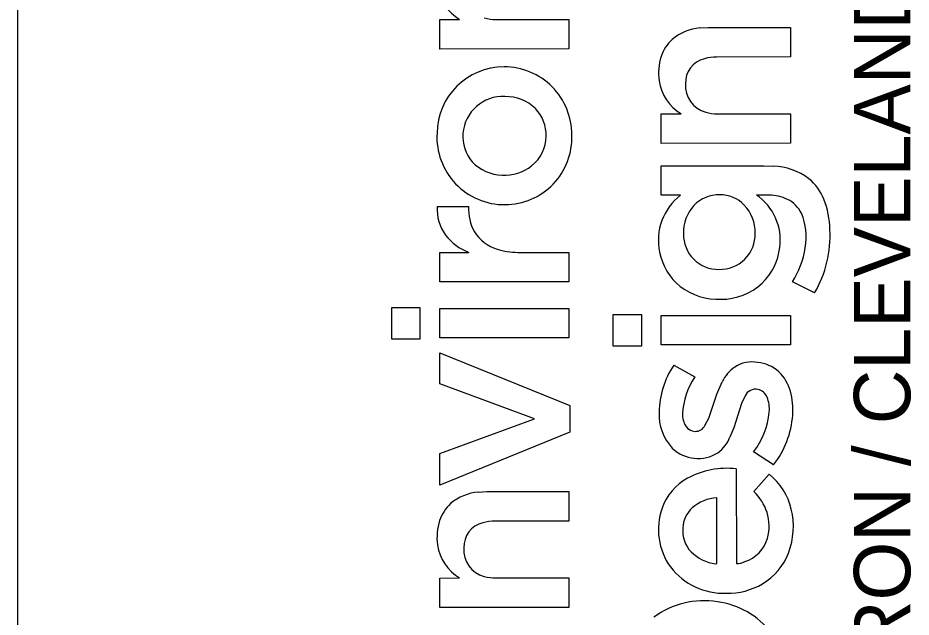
# Model space of a CAD drawing. Extents: x -0.2 to 34, y 0 to 22.
# Drawn here: x 32 to 32.901, y 2.778 to 3.382 of the extents above; entities that cross this region are included whole.
import ezdxf

# ---------------------------------------------------------------- set-up
doc = ezdxf.new("R2010")
doc.units = 0
doc.layers.add('SH_Border', color=7, linetype='Continuous')
doc.layers.add('SH_Data', color=7, linetype='Continuous')

msp = doc.modelspace()

# ---------------------------------------------------------------- linework, layer by layer
at = {"layer": 'SH_Border'}
for p, q in [((32.42542, 3.38066), (32.44552, 3.38071)), ((32.42542, 3.35086), (32.42542, 3.38066)), ((32.48222, 3.38071), (32.55569, 3.38071)), ((32.55569, 3.38071), (32.55571, 3.35096)), ((32.68784, 3.3722), (32.69634, 3.37266)), ((32.69634, 3.37266), (32.77916, 3.37266)), ((32.77916, 3.37266), (32.77917, 3.34287)), ((32.55571, 3.35096), (32.42542, 3.35086)), ((32.77917, 3.34287), (32.70485, 3.3428)), ((32.64888, 3.2855), (32.66897, 3.28555)), ((32.64888, 3.25569), (32.64888, 3.2855)), ((32.70568, 3.28555), (32.77915, 3.28555)), ((32.77915, 3.28555), (32.77917, 3.25579)), ((32.77917, 3.25579), (32.64888, 3.25569)), ((32.6489, 3.20336), (32.64889, 3.23322)), ((32.64889, 3.23322), (32.75236, 3.23322)), ((32.75236, 3.23322), (32.76191, 3.23285)), ((32.66836, 3.20336), (32.6489, 3.20336)), ((32.75763, 3.20356), (32.74487, 3.20361)), ((32.42299, 3.19193), (32.45454, 3.19193)), ((32.42542, 3.14577), (32.45473, 3.14579)), ((32.42542, 3.11593), (32.42542, 3.14577)), ((32.50413, 3.14581), (32.55571, 3.14573)), ((32.55571, 3.14573), (32.55565, 3.11593)), ((32.55565, 3.11593), (32.42542, 3.11593)), ((32.8036, 3.10491), (32.7812, 3.11598)), ((32.37705, 3.05818), (32.37705, 3.09026)), ((32.37705, 3.09026), (32.40543, 3.09026)), ((32.40543, 3.09026), (32.40543, 3.05818)), ((32.42542, 3.05942), (32.42542, 3.08928)), ((32.42542, 3.08928), (32.55571, 3.08928)), ((32.55571, 3.08928), (32.55571, 3.05942)), ((32.60051, 3.05111), (32.60051, 3.08319)), ((32.60051, 3.08319), (32.62889, 3.08319)), ((32.62889, 3.08319), (32.62889, 3.05111)), ((32.64888, 3.05234), (32.64888, 3.0822)), ((32.64888, 3.0822), (32.77917, 3.0822)), ((32.77917, 3.0822), (32.77917, 3.05234)), ((32.40543, 3.05818), (32.37705, 3.05818)), ((32.55571, 3.05942), (32.42542, 3.05942)), ((32.62889, 3.05111), (32.60051, 3.05111)), ((32.77917, 3.05234), (32.64888, 3.05234)), ((32.42542, 3.01327), (32.42542, 3.0446)), ((32.42542, 3.0446), (32.5567, 2.9913)), ((32.66151, 3.03207), (32.68268, 3.02025)), ((32.52117, 2.97798), (32.42542, 3.01327)), ((32.70483, 3.00258), (32.71036, 3.01526)), ((32.69675, 2.97868), (32.70483, 3.00258)), ((32.73342, 3.00101), (32.72985, 2.9933)), ((32.5567, 2.9913), (32.5567, 2.96441)), ((32.72985, 2.9933), (32.72213, 2.96882)), ((32.42542, 2.94294), (32.52117, 2.97798)), ((32.69299, 2.97117), (32.69675, 2.97868)), ((32.5567, 2.96441), (32.42542, 2.91086)), ((32.72213, 2.96882), (32.71822, 2.95921)), ((32.42542, 2.91086), (32.42542, 2.94294)), ((32.76214, 2.93141), (32.74198, 2.94469)), ((32.72453, 2.92747), (32.72463, 2.83195)), ((32.74228, 2.90465), (32.75768, 2.922)), ((32.46439, 2.90397), (32.47289, 2.90443)), ((32.47289, 2.90443), (32.55571, 2.90443)), ((32.55571, 2.90443), (32.55571, 2.87465)), ((32.70489, 2.83182), (32.70489, 2.89834)), ((32.55571, 2.87465), (32.4814, 2.87457)), ((32.70361, 2.83165), (32.70489, 2.83182)), ((32.42542, 2.81728), (32.44552, 2.81733)), ((32.42542, 2.78747), (32.42542, 2.81728)), ((32.48222, 2.81733), (32.55569, 2.81733)), ((32.55569, 2.81733), (32.55571, 2.78756)), ((32.55571, 2.78756), (32.42542, 2.78747))]:
    msp.add_line(p, q, dxfattribs=at)
for points in [[(32.42542, 3.35086), (32.42542, 3.38066), (32.44552, 3.38071)], [(32.48222, 3.38071), (32.55569, 3.38071), (32.55571, 3.35096), (32.42542, 3.35086)], [(32.68784, 3.3722), (32.69634, 3.37266), (32.77916, 3.37266), (32.77917, 3.34287), (32.70485, 3.3428)], [(32.64888, 3.25569), (32.64888, 3.2855), (32.66897, 3.28555)], [(32.70568, 3.28555), (32.77915, 3.28555), (32.77917, 3.25579), (32.64888, 3.25569)], [(32.66836, 3.20336), (32.6489, 3.20336), (32.64889, 3.23322), (32.75236, 3.23322), (32.76191, 3.23285)], [(32.75763, 3.20356), (32.74487, 3.20361)], [(32.42299, 3.19193), (32.45454, 3.19193)], [(32.50413, 3.14581), (32.55571, 3.14573), (32.55565, 3.11593), (32.42542, 3.11593)], [(32.42542, 3.11593), (32.42542, 3.14577), (32.45473, 3.14579)], [(32.8036, 3.10491), (32.7812, 3.11598)], [(32.66151, 3.03207), (32.68268, 3.02025)], [(32.69299, 2.97117), (32.69675, 2.97868), (32.70483, 3.00258), (32.71036, 3.01526)], [(32.73342, 3.00101), (32.72985, 2.9933), (32.72213, 2.96882), (32.71822, 2.95921)], [(32.76214, 2.93141), (32.74198, 2.94469)], [(32.72453, 2.92747), (32.72463, 2.83195)], [(32.74228, 2.90465), (32.75768, 2.922)], [(32.46439, 2.90397), (32.47289, 2.90443), (32.55571, 2.90443), (32.55571, 2.87465), (32.4814, 2.87457)], [(32.70361, 2.83165), (32.70489, 2.83182), (32.70489, 2.89834)], [(32.42542, 2.78747), (32.42542, 2.81728), (32.44552, 2.81733)], [(32.48222, 2.81733), (32.55569, 2.81733), (32.55571, 2.78756), (32.42542, 2.78747)]]:
    msp.add_lwpolyline(points, dxfattribs=at)
for points in [[(32.37705, 3.05818), (32.37705, 3.09026), (32.40543, 3.09026), (32.40543, 3.05818)], [(32.42542, 3.05942), (32.42542, 3.08928), (32.55571, 3.08928), (32.55571, 3.05942)], [(32.60051, 3.05111), (32.60051, 3.08319), (32.62889, 3.08319), (32.62889, 3.05111)], [(32.64888, 3.05234), (32.64888, 3.0822), (32.77917, 3.0822), (32.77917, 3.05234)], [(32.42542, 2.91086), (32.42542, 2.94294), (32.52117, 2.97798), (32.42542, 3.01327), (32.42542, 3.0446), (32.5567, 2.9913), (32.5567, 2.96441)]]:
    msp.add_lwpolyline(points, close=True, dxfattribs=at)
for centre, radius, start, end in [((32.47027, 3.42141), 0.04763, 188.96462, 238.69865), ((32.47027, 3.42141), 0.04763, 188.96462, 238.69865), ((32.48183, 3.42286), 0.04215, 254.08913, 270.52838), ((32.48183, 3.42286), 0.04215, 254.08913, 270.52838), ((32.69216, 3.32251), 0.04988, 94.97056, 130.22484), ((32.69216, 3.32251), 0.04988, 94.97056, 130.22484), ((32.68694, 3.33085), 0.04016, 132.22383, 161.68229), ((32.68694, 3.33085), 0.04016, 132.22383, 161.68229), ((32.70217, 3.32642), 0.05602, 162.27398, 187.79173), ((32.70217, 3.32642), 0.05602, 162.27398, 187.79173), ((32.70453, 3.29679), 0.04601, 89.60515, 105.33026), ((32.70453, 3.29679), 0.04601, 89.60515, 105.33026), ((32.69828, 3.31689), 0.02498, 103.68683, 182.21395), ((32.69828, 3.31689), 0.02498, 103.68683, 182.21395), ((32.49014, 3.26543), 0.0674, 89.84756, 179.64047), ((32.49014, 3.26543), 0.0674, 89.84756, 179.64047), ((32.49057, 3.26474), 0.0681, 359.54009, 90.21138), ((32.49057, 3.26474), 0.0681, 359.54009, 90.21138), ((32.69372, 3.32624), 0.04763, 188.96462, 238.69865), ((32.69372, 3.32624), 0.04763, 188.96462, 238.69865), ((32.7008, 3.31381), 0.02757, 175.58441, 255.13816), ((32.7008, 3.31381), 0.02757, 175.58441, 255.13816), ((32.48923, 3.26263), 0.0404, 87.04809, 175.57259), ((32.48923, 3.26263), 0.0404, 87.04809, 175.57259), ((32.49204, 3.25999), 0.04299, 45.84264, 90.98008), ((32.49204, 3.25999), 0.04299, 45.84264, 90.98008), ((32.49458, 3.26421), 0.03821, 357.88569, 44.15902), ((32.49458, 3.26421), 0.03821, 357.88569, 44.15902), ((32.70529, 3.32769), 0.04215, 254.08913, 270.52838), ((32.70529, 3.32769), 0.04215, 254.08913, 270.52838), ((32.49083, 3.26209), 0.06819, 176.8344, 270.40384), ((32.49083, 3.26209), 0.06819, 176.8344, 270.40384), ((32.48729, 3.2625), 0.03848, 175.15378, 221.14706), ((32.48729, 3.2625), 0.03848, 175.15378, 221.14706), ((32.49123, 3.26139), 0.06749, 270.06243, 2.37759), ((32.49123, 3.26139), 0.06749, 270.06243, 2.37759), ((32.49446, 3.26318), 0.0383, 308.28936, 359.43468), ((32.49446, 3.26318), 0.0383, 308.28936, 359.43468), ((32.48919, 3.26607), 0.04228, 223.09994, 268.80895), ((32.48919, 3.26607), 0.04228, 223.09994, 268.80895), ((32.49096, 3.2679), 0.04418, 266.56515, 308.06078), ((32.49096, 3.2679), 0.04418, 266.56515, 308.06078), ((32.75907, 3.16789), 0.06503, 53.40344, 87.49062), ((32.75907, 3.16789), 0.06503, 53.40344, 87.49062), ((32.76517, 3.18039), 0.05141, 21.60748, 50.5577), ((32.76517, 3.18039), 0.05141, 21.60748, 50.5577), ((32.70292, 3.15813), 0.05692, 127.37482, 192.22468), ((32.70292, 3.15813), 0.05692, 127.37482, 192.22468), ((32.70693, 3.16927), 0.0346, 88.47302, 136.42562), ((32.70693, 3.16927), 0.0346, 88.47302, 136.42562), ((32.70814, 3.16963), 0.03424, 44.27195, 90.47623), ((32.70814, 3.16963), 0.03424, 44.27195, 90.47623), ((32.71421, 3.15829), 0.05472, 352.1125, 55.92295), ((32.71421, 3.15829), 0.05472, 352.1125, 55.92295), ((32.75666, 3.15725), 0.04633, 65.01687, 88.8011), ((32.75666, 3.15725), 0.04633, 65.01687, 88.8011), ((32.7626, 3.17155), 0.03085, 26.26808, 63.80301), ((32.7626, 3.17155), 0.03085, 26.26808, 63.80301), ((32.73069, 3.16714), 0.08835, 1.15143, 21.3627), ((32.73069, 3.16714), 0.08835, 1.15143, 21.3627), ((32.46616, 3.18882), 0.04329, 175.87313, 216.34747), ((32.46616, 3.18882), 0.04329, 175.87313, 216.34747), ((32.50087, 3.18948), 0.04639, 176.9688, 209.60636), ((32.50087, 3.18948), 0.04639, 176.9688, 209.60636), ((32.71141, 3.16602), 0.0401, 137.46739, 182.33237), ((32.71141, 3.16602), 0.0401, 137.46739, 182.33237), ((32.70368, 3.166), 0.03996, 358.57141, 43.53765), ((32.70368, 3.166), 0.03996, 358.57141, 43.53765), ((32.73565, 3.16154), 0.05953, 349.30734, 23.43071), ((32.73565, 3.16154), 0.05953, 349.30734, 23.43071), ((32.47466, 3.19716), 0.05511, 218.09809, 248.7907), ((32.47466, 3.19716), 0.05511, 218.09809, 248.7907), ((32.49514, 3.18814), 0.04079, 211.94466, 253.2028), ((32.49514, 3.18814), 0.04079, 211.94466, 253.2028), ((32.70645, 3.1637), 0.03511, 178.88208, 271.08374), ((32.70645, 3.1637), 0.03511, 178.88208, 271.08374), ((32.70818, 3.16404), 0.03546, 268.27882, 1.55016), ((32.70818, 3.16404), 0.03546, 268.27882, 1.55016), ((32.70538, 3.16244), 0.11383, 329.6388, 3.25998), ((32.70538, 3.16244), 0.11383, 329.6388, 3.25998), ((32.50465, 3.2165), 0.07069, 252.46555, 269.57296), ((32.50465, 3.2165), 0.07069, 252.46555, 269.57296), ((32.70463, 3.15696), 0.05837, 190.75182, 231.28919), ((32.70463, 3.15696), 0.05837, 190.75182, 231.28919), ((32.70988, 3.15708), 0.05887, 313.74196, 353.8554), ((32.70988, 3.15708), 0.05887, 313.74196, 353.8554), ((32.70738, 3.16334), 0.08771, 327.31495, 351.57478), ((32.70738, 3.16334), 0.08771, 327.31495, 351.57478), ((32.70632, 3.16112), 0.06269, 232.46061, 272.59022), ((32.70632, 3.16112), 0.06269, 232.46061, 272.59022), ((32.70954, 3.15901), 0.06051, 269.6361, 312.70877), ((32.70954, 3.15901), 0.06051, 269.6361, 312.70877), ((32.73636, 2.98258), 0.08973, 146.53104, 178.7571), ((32.73636, 2.98258), 0.08973, 146.53104, 178.7571), ((32.74661, 2.99713), 0.04053, 125.51182, 153.41595), ((32.74661, 2.99713), 0.04053, 125.51182, 153.41595), ((32.7406, 3.0026), 0.03263, 80.17192, 122.51969), ((32.7406, 3.0026), 0.03263, 80.17192, 122.51969), ((32.74278, 2.99824), 0.03667, 47.79344, 84.68918), ((32.74278, 2.99824), 0.03667, 47.79344, 84.68918), ((32.74519, 2.9789), 0.07495, 146.51121, 176.91007), ((32.74519, 2.9789), 0.07495, 146.51121, 176.91007), ((32.73788, 2.9946), 0.04267, 14.9966, 46.20632), ((32.73788, 2.9946), 0.04267, 14.9966, 46.20632), ((32.74384, 2.99631), 0.01143, 76.66094, 155.7053), ((32.74384, 2.99631), 0.01143, 76.66094, 155.7053), ((32.74397, 2.99511), 0.01256, 21.5098, 78.52618), ((32.74397, 2.99511), 0.01256, 21.5098, 78.52618), ((32.71044, 2.98674), 0.07121, 355.83062, 15.39138), ((32.71044, 2.98674), 0.07121, 355.83062, 15.39138), ((32.72592, 2.98766), 0.03209, 354.57264, 22.06805), ((32.72592, 2.98766), 0.03209, 354.57264, 22.06805), ((32.69666, 2.98238), 0.05005, 177.53659, 222.79318), ((32.69666, 2.98238), 0.05005, 177.53659, 222.79318), ((32.6931, 2.98233), 0.02276, 178.47474, 211.08679), ((32.6931, 2.98233), 0.02276, 178.47474, 211.08679), ((32.68248, 2.99149), 0.0757, 321.81101, 354.79685), ((32.68248, 2.99149), 0.0757, 321.81101, 354.79685), ((32.68952, 2.9882), 0.09219, 321.9777, 355.87384), ((32.68952, 2.9882), 0.09219, 321.9777, 355.87384), ((32.68331, 2.9767), 0.01148, 212.23676, 268.37769), ((32.68331, 2.9767), 0.01148, 212.23676, 268.37769), ((32.68342, 2.97589), 0.01067, 267.71603, 333.73375), ((32.68342, 2.97589), 0.01067, 267.71603, 333.73375), ((32.68098, 2.9758), 0.04077, 308.08772, 335.98736), ((32.68098, 2.9758), 0.04077, 308.08772, 335.98736), ((32.68599, 2.97535), 0.0375, 225.98539, 302.47965), ((32.68599, 2.97535), 0.0375, 225.98539, 302.47965), ((32.7152, 2.84414), 0.08384, 83.61499, 118.28755), ((32.7152, 2.84414), 0.08384, 83.61499, 118.28755), ((32.71744, 2.87167), 0.06443, 13.53365, 51.36148), ((32.71744, 2.87167), 0.06443, 13.53365, 51.36148), ((32.70239, 2.86906), 0.05583, 118.83082, 160.62438), ((32.70239, 2.86906), 0.05583, 118.83082, 160.62438), ((32.46871, 2.85428), 0.04988, 94.96958, 130.22249), ((32.46871, 2.85428), 0.04988, 94.96958, 130.22249), ((32.70378, 2.86556), 0.05486, 19.03571, 45.44059), ((32.70378, 2.86556), 0.05486, 19.03571, 45.44059), ((32.46348, 2.86263), 0.04015, 132.22192, 161.68183), ((32.46348, 2.86263), 0.04015, 132.22192, 161.68183), ((32.70785, 2.85609), 0.04235, 94.00805, 130.88169), ((32.70785, 2.85609), 0.04235, 94.00805, 130.88169), ((32.71041, 2.86612), 0.06437, 160.52012, 215.78311), ((32.71041, 2.86612), 0.06437, 160.52012, 215.78311), ((32.70048, 2.86628), 0.02985, 132.98507, 177.179), ((32.70048, 2.86628), 0.02985, 132.98507, 177.179), ((32.71069, 2.8697), 0.047, 344.60586, 17.007), ((32.71069, 2.8697), 0.047, 344.60586, 17.007), ((32.70635, 2.86921), 0.07579, 339.3542, 13.37853), ((32.70635, 2.86921), 0.07579, 339.3542, 13.37853), ((32.47872, 2.85819), 0.05601, 162.27355, 187.79185), ((32.47872, 2.85819), 0.05601, 162.27355, 187.79185), ((32.48108, 2.82856), 0.04601, 89.60494, 105.3284), ((32.48108, 2.82856), 0.04601, 89.60494, 105.3284), ((32.47482, 2.84867), 0.02498, 103.68646, 182.21874), ((32.47482, 2.84867), 0.02498, 103.68646, 182.21874), ((32.7017, 2.86503), 0.03115, 175.00126, 223.28301), ((32.7017, 2.86503), 0.03115, 175.00126, 223.28301), ((32.7224, 2.86715), 0.03504, 288.00773, 343.55078), ((32.7224, 2.86715), 0.03504, 288.00773, 343.55078), ((32.47026, 2.85802), 0.04762, 188.96199, 238.70369), ((32.47026, 2.85802), 0.04762, 188.96199, 238.70369), ((32.47735, 2.84558), 0.02756, 175.58538, 255.14386), ((32.47735, 2.84558), 0.02756, 175.58538, 255.14386), ((32.70891, 2.87363), 0.04231, 225.06188, 262.79738), ((32.70891, 2.87363), 0.04231, 225.06188, 262.79738), ((32.71894, 2.8652), 0.0626, 300.94269, 338.73225), ((32.71894, 2.8652), 0.0626, 300.94269, 338.73225), ((32.72474, 2.85216), 0.02021, 269.7003, 294.8711), ((32.72474, 2.85216), 0.02021, 269.7003, 294.8711), ((32.71253, 2.87054), 0.06872, 217.74516, 271.65431), ((32.71253, 2.87054), 0.06872, 217.74516, 271.65431), ((32.48183, 2.85948), 0.04215, 254.09162, 270.52835), ((32.48183, 2.85948), 0.04215, 254.09162, 270.52835), ((32.71549, 2.87241), 0.07056, 269.20477, 300.33412), ((32.71549, 2.87241), 0.07056, 269.20477, 300.33412), ((32.69229, 2.70792), 0.08641, 81.19402, 125.99844), ((32.69229, 2.70792), 0.08641, 81.19402, 125.99844), ((32.69458, 2.71132), 0.08272, 37.85208, 82.40204), ((32.69458, 2.71132), 0.08272, 37.85208, 82.40204)]:
    msp.add_arc(centre, radius, start, end, dxfattribs=at)
at = {"layer": 'SH_Data'}
msp.add_line((32, 0.5), (32, 21.5), dxfattribs=at)

# ---------------------------------------------------------------- texts
at = {"layer": 'SH_Border'}
msp.add_text('AKRON / CLEVELAND / COLUMBUS', height=0.056969, rotation=90, dxfattribs=at).set_placement((32.90012, 2.638))

doc.saveas('drawing.dxf')
